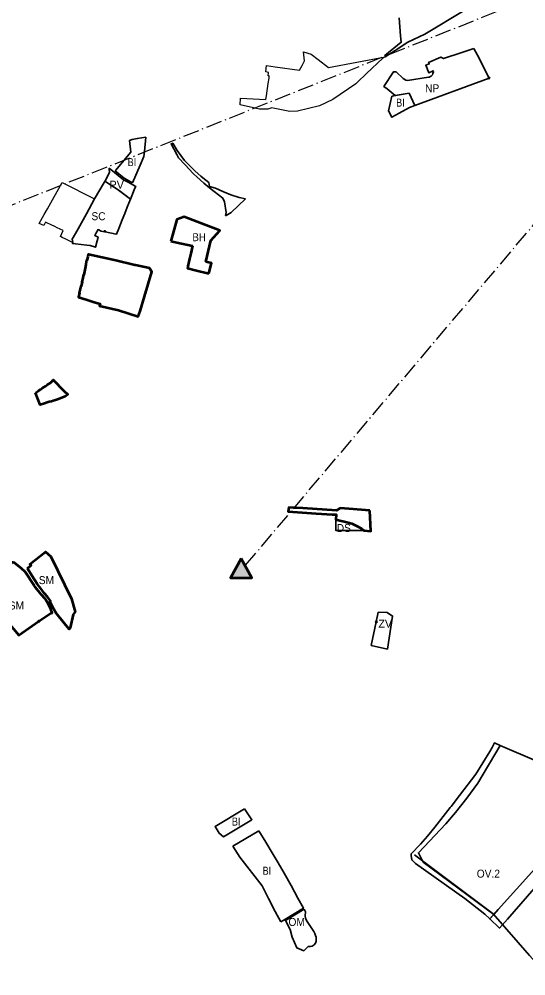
# Model space of a CAD drawing. Extents: x -650276 to -642489, y -1074311 to -1066658.
# Drawn here: x -646929 to -646170, y -1071706 to -1070271 of the extents above; entities that cross this region are included whole.
import ezdxf

# ---------------------------------------------------------------- set-up
doc = ezdxf.new("R2010")
doc.units = 0
doc.header["$LTSCALE"] = 4.8
doc.header["$PDMODE"] = 32
doc.header["$PDSIZE"] = 2.4
doc.linetypes.add('DOT_DASHED', pattern=[7.7, 5, -1.2, 0.3, -1.2])
for name, color, linetype, lineweight in [('1', 7, 'Continuous', 35), ('11', 7, 'Continuous', 35), ('12', 7, 'Continuous', 35), ('15', 7, 'Continuous', 35), ('17', 7, 'Continuous', 35), ('18', 7, 'Continuous', 35), ('2', 7, 'Continuous', 35), ('24', 7, 'Continuous', 35), ('40', 7, 'Continuous', 35), ('48', 7, 'Continuous', 35), ('54', 7, 'Continuous', 35), ('55', 7, 'Continuous', 53), ('60', 7, 'Continuous', 53), ('61', 7, 'Continuous', 25)]:
    doc.layers.add(name, color=color, linetype=linetype, lineweight=lineweight)
doc.layers.add('62', color=7, linetype='Continuous')
doc.layers.add('63', color=7, linetype='Continuous')

msp = doc.modelspace()

# ---------------------------------------------------------------- hatches: boundary and pattern name
at = {"layer": '55'}
msp.add_hatch(color=256, dxfattribs=at).paths.add_polyline_path([(-646596.857, -1071079.969), (-646612.808, -1071108.615), (-646580.424, -1071108.615)])

# ---------------------------------------------------------------- linework, layer by layer
at = {"layer": '1'}
msp.add_line((-646665.42, -1070647.54), (-646645.03, -1070652.34), dxfattribs=at)
for points in [[(-646655.95, -1070577.64), (-646682.29, -1070567.36), (-646692.98, -1070571.45), (-646701.87, -1070603.92)], [(-646649.71, -1070634.85), (-646642.32, -1070603.3), (-646628.69, -1070588.27), (-646655.95, -1070577.64)], [(-646701.87, -1070603.92), (-646693.18, -1070605.83), (-646669.59, -1070611.01), (-646672.13, -1070622.41), (-646673.91, -1070630.38), (-646676.414, -1070641.58)], [(-646676.414, -1070641.58), (-646676.81, -1070643.36), (-646677.13, -1070644.78), (-646665.42, -1070647.54)], [(-646645.03, -1070652.34), (-646641.09, -1070636.89), (-646649.71, -1070634.85)]]:
    msp.add_lwpolyline(points, dxfattribs=at)
at = {"layer": '11'}
msp.add_lwpolyline([(-646066.165, -1071422.155), (-646153.5, -1071383.85), (-646208.577, -1071360.044), (-646241.68, -1071416.887), (-646258.487, -1071439.265), (-646275.615, -1071460.886), (-646289.976, -1071477.514), (-646330.914, -1071521.11), (-646324, -1071535), (-646217.978, -1071613.552), (-646211.407, -1071606.247), (-646156.471, -1071545.166), (-646094.063, -1071471.007)], close=True, dxfattribs=at)
at = {"layer": '12'}
msp.add_lwpolyline([(-646502.39, -1071605.72), (-646530.27, -1071622.79), (-646522.99, -1071636.22), (-646520.32, -1071647.59), (-646513.43, -1071663.64), (-646502.53, -1071667.82), (-646496.06, -1071661.5), (-646492.89, -1071661.75), (-646490.07, -1071660.88), (-646487.36, -1071659.1), (-646485.29, -1071656.53), (-646484.15, -1071653.38), (-646483.97, -1071650.63), (-646484.38, -1071647.41), (-646485.2, -1071644.85), (-646486.31, -1071641.97), (-646487.56, -1071639.23), (-646497.83, -1071624.02), (-646499.829, -1071620.704), (-646500.289, -1071619.291), (-646500.83, -1071615.62), (-646500.34, -1071609.66)], close=True, dxfattribs=at)
at = {"layer": '15'}
for points in [[(-646623.95, -1070529.36), (-646634.85, -1070524.43), (-646644.2, -1070522.08), (-646645.31, -1070515.85), (-646654, -1070509), (-646656.83, -1070506.66), (-646665.457, -1070499.019), (-646667.42, -1070497.28), (-646681.6, -1070482.89), (-646692.74, -1070468.28), (-646699.26, -1070457.2), (-646701.65, -1070457.93), (-646693.119, -1070474.009), (-646690.316, -1070479.212), (-646680.44, -1070489.669), (-646668.361, -1070502.459), (-646667.369, -1070503.36), (-646662.895, -1070507.428), (-646652.352, -1070517.013), (-646643.895, -1070524.284), (-646637.158, -1070529.564), (-646624.211, -1070539.711), (-646621.729, -1070545.248), (-646619.34, -1070560.95), (-646619.99, -1070565.54), (-646619.15, -1070565.53), (-646611.41, -1070560.96), (-646590.2, -1070540.66), (-646599.81, -1070538.51), (-646611.88, -1070534.82)], [(-646275.615, -1071460.886), (-646258.487, -1071439.265), (-646241.68, -1071416.887), (-646208.577, -1071360.044), (-646217.049, -1071356.382), (-646220.61, -1071363.16), (-646223.77, -1071369.24), (-646245.1, -1071403.04), (-646269.2, -1071435.22), (-646281.99, -1071451.4), (-646283.52, -1071453.34), (-646293.87, -1071466.43), (-646306.14, -1071482.86), (-646317.52, -1071496.12), (-646327.97, -1071508.29), (-646341.88, -1071522.81), (-646341.66, -1071524.87), (-646340.93, -1071531.64), (-646335.3, -1071537.05), (-646261.46, -1071589.38), (-646231.43, -1071613.06), (-646223.928, -1071620.168), (-646217.978, -1071613.552), (-646324, -1071535), (-646330.914, -1071521.11), (-646289.976, -1071477.514), (-646275.615, -1071460.886)]]:
    msp.add_lwpolyline(points, close=True, dxfattribs=at)
for points in [[(-646794.59, -1070494.62), (-646794.53, -1070495.7), (-646793.75, -1070501.26), (-646800.6, -1070513.43), (-646800.94, -1070514.04)], [(-646755.84, -1070524.5), (-646754.52, -1070522.08), (-646765.96, -1070515.75), (-646770.95, -1070512.94), (-646773, -1070511.96), (-646794.59, -1070494.62)], [(-646800.94, -1070514.04), (-646788, -1070522.49), (-646782.63, -1070526.02)], [(-646782.63, -1070526.02), (-646779.68, -1070527.87), (-646762.71, -1070540.85), (-646755.84, -1070524.5)], [(-646156.471, -1071545.166), (-646211.407, -1071606.247), (-646223.928, -1071620.168), (-646209.322, -1071634.004), (-646197.398, -1071620.579), (-646077.593, -1071482.499)]]:
    msp.add_lwpolyline(points, dxfattribs=at)
at = {"layer": '17'}
msp.add_lwpolyline([(-646802.19, -1070516.26), (-646816.42, -1070540.49), (-646828.45, -1070562.89), (-646841.16, -1070585.79), (-646844.76, -1070592.54), (-646849.72, -1070600.98), (-646848.99, -1070606.28), (-646849.59, -1070607.4), (-646844.96, -1070607.98), (-646827.88, -1070610.12), (-646822.99, -1070610.51), (-646815.05, -1070613.14), (-646812.5, -1070603.78), (-646811.5, -1070600.29), (-646810.82, -1070598.23), (-646816.11, -1070595.8), (-646814.52, -1070592.78), (-646811.06, -1070586.67), (-646806.41, -1070589), (-646802.06, -1070589.93), (-646801.73, -1070588.37), (-646800.13, -1070588.71), (-646800.47, -1070590.28), (-646784.18, -1070593.76), (-646784, -1070593.34), (-646783.59, -1070593.52), (-646779.9, -1070584.92), (-646774.91, -1070571.88), (-646771.17, -1070562.7), (-646767.63, -1070553.09), (-646762.71, -1070540.85), (-646782.63, -1070526.02), (-646788, -1070522.49), (-646800.94, -1070514.04)], close=True, dxfattribs=at)
at = {"layer": '18'}
for points in [[(-646881.89, -1071077.03), (-646890.12, -1071069.67), (-646913.49, -1071088.22), (-646911.58, -1071089.9), (-646917.04, -1071094.75), (-646910.53, -1071105.18), (-646902.62, -1071117.58), (-646895.56, -1071126.84), (-646892.339, -1071131.481), (-646886.78, -1071137.25), (-646882.37, -1071143.39), (-646883.63, -1071144.15), (-646873.89, -1071161.58), (-646861.58, -1071177.05), (-646854.49, -1071185.87), (-646852.86, -1071183.98), (-646848.58, -1071163.95), (-646845.39, -1071159.98), (-646850.93, -1071140.54)], [(-646951.831, -1071107.765), (-646955.138, -1071114.466), (-646962.471, -1071129.325), (-646948.286, -1071172.534), (-646929.64, -1071194.58), (-646899.85, -1071173.89), (-646881.68, -1071161.83), (-646879.91, -1071161.24), (-646881.97, -1071155.84), (-646887.07, -1071145.66), (-646890.59, -1071140.39), (-646896.62, -1071133.93), (-646904.64, -1071123.54), (-646906.72, -1071120.46), (-646920.54, -1071099.98), (-646925.88, -1071094.68), (-646936.51, -1071086.33), (-646940.67, -1071085.15), (-646940.67, -1071085.15)]]:
    msp.add_lwpolyline(points, close=True, dxfattribs=at)
msp.add_point((-646899.85, -1071173.89), dxfattribs=at)
at = {"layer": '2'}
msp.add_line((-646609.21, -1071510.98), (-646570, -1071488.38), dxfattribs=at)
for points in [[(-646344.93, -1070382.33), (-646336.25, -1070400.875), (-646344.26, -1070403.84), (-646359.769, -1070412.361), (-646370.56, -1070418.29), (-646375.63, -1070408.76), (-646370.624, -1070386.792)], [(-646591.65, -1071454.91), (-646635.79, -1071481.6), (-646629.37, -1071491.74), (-646623.18, -1071496.99), (-646580.58, -1071471.48)]]:
    msp.add_lwpolyline(points, close=True, dxfattribs=at)
for points in [[(-646739.74, -1070447.98), (-646752.29, -1070450.28), (-646760.03, -1070451.56), (-646763.94, -1070452.95), (-646761.8, -1070470.4), (-646785.15, -1070498.05), (-646785.5, -1070498.47)], [(-646759.42, -1070516.37), (-646747.89, -1070489.87), (-646742.37, -1070477.2), (-646741.33, -1070469.79), (-646739.74, -1070447.98)], [(-646785.5, -1070498.47), (-646771.9, -1070509.4), (-646759.42, -1070516.37)], [(-646570, -1071488.38), (-646559.53, -1071505.12), (-646550.23, -1071520.88), (-646541.14, -1071536.3), (-646532.04, -1071551.72), (-646521.8, -1071570.34), (-646511.47, -1071589.11), (-646503.31, -1071603.95), (-646531.2, -1071621.07), (-646537.28, -1071624.8)], [(-646537.28, -1071624.8), (-646545.89, -1071609.07), (-646555.78, -1071589.66), (-646565.17, -1071570.4), (-646598.63, -1071527.8), (-646609.21, -1071510.98)]]:
    msp.add_lwpolyline(points, dxfattribs=at)
at = {"layer": '24'}
msp.add_lwpolyline([(-646454.59, -1071021.54), (-646454.59, -1071038), (-646412.54, -1071038.01), (-646415.61, -1071035.4), (-646421.58, -1071031.81), (-646430.91, -1071027.44)], close=True, dxfattribs=at)
at = {"layer": '40'}
for points in [[(-646377.5, -1071215.56), (-646369.76, -1071166.06), (-646377.87, -1071160.66), (-646391.07, -1071160.52), (-646394.05, -1071174.83)], [(-646394.05, -1071174.83), (-646401.64, -1071210.18), (-646377.5, -1071215.56)]]:
    msp.add_lwpolyline(points, dxfattribs=at)
msp.add_point((-646394.05, -1071174.83), dxfattribs=at)
at = {"layer": '48'}
msp.add_lwpolyline([(-646359.89, -1070269.01), (-646357.73, -1070296.13), (-646356.8, -1070305.73), (-646381.25, -1070325.85), (-646380.69, -1070327.47), (-646365.63, -1070318.37), (-646346.57, -1070305.88), (-646321.24, -1070293.85), (-646259.91, -1070256.89)], dxfattribs=at)
msp.add_lwpolyline([(-646247.667, -1070315.004), (-646267.3, -1070321.61), (-646293.14, -1070330.3), (-646297.4, -1070328.01), (-646315.84, -1070336.13), (-646314.84, -1070338.41), (-646319.95, -1070340.42), (-646315.46, -1070351.67), (-646308.791, -1070348.855), (-646308.59, -1070350.22), (-646309.18, -1070352.77), (-646309.99, -1070354.58), (-646311.82, -1070356.89), (-646314.6, -1070358.05), (-646315.7, -1070358.27), (-646347.49, -1070363.01), (-646349.76, -1070362.69), (-646353.81, -1070360.18), (-646364.34, -1070350.19), (-646368.4, -1070350.41), (-646382.67, -1070371.94), (-646377.86, -1070375.71), (-646365.7, -1070385.89), (-646344.93, -1070382.33), (-646336.35, -1070400.9), (-646225.15, -1070359.46), (-646242.56, -1070325.1)], close=True, dxfattribs=at)
msp.add_point((-646225.15, -1070359.46), dxfattribs=at)
at = {"layer": '54'}
msp.add_lwpolyline([(-646336.784, -1071524.232), (-646218.737, -1071612.767), (-646164.374, -1071674.897), (-645904.456, -1071961.331), (-645718.199, -1072151.712), (-645526.944, -1072343.922), (-645538, -1072384), (-645459, -1072440), (-645389, -1072483), (-645335, -1072526), (-645287, -1072569), (-645227, -1072617), (-645139.573, -1072694.628), (-645084.365, -1072788.086)], dxfattribs=at)
at = {"layer": '55', "linetype": 'DOT_DASHED', "lineweight": 25}
for p, q in [((-647060.176, -1070597.455), (-645765.418, -1070080.935)), ((-646590, -1071090), (-645744.292, -1070089.84))]:
    msp.add_line(p, q, dxfattribs=at)
at = {"layer": '55'}
msp.add_lwpolyline([(-646596.857, -1071079.969), (-646612.808, -1071108.615), (-646580.424, -1071108.615)], close=True, dxfattribs=at)
at = {"layer": '60'}
for points in [[(-646655.95, -1070577.64), (-646682.29, -1070567.36), (-646692.98, -1070571.45), (-646701.87, -1070603.92)], [(-646649.71, -1070634.85), (-646642.32, -1070603.3), (-646628.69, -1070588.27), (-646655.95, -1070577.64)], [(-646701.87, -1070603.92), (-646693.18, -1070605.83), (-646669.59, -1070611.01)], [(-646669.59, -1070611.01), (-646672.13, -1070622.41), (-646673.91, -1070630.38), (-646676.414, -1070641.58)], [(-646676.414, -1070641.58), (-646676.81, -1070643.36), (-646677.13, -1070644.78), (-646665.42, -1070647.54), (-646645.03, -1070652.34)], [(-646645.03, -1070652.34), (-646641.09, -1070636.89), (-646649.71, -1070634.85)]]:
    msp.add_lwpolyline(points, dxfattribs=at)
for points in [[(-646825.54, -1070624.03), (-646826.12, -1070623.9), (-646826.45, -1070627.3), (-646827.98, -1070632.83), (-646828.22, -1070632.77), (-646829.55, -1070638.78), (-646829.55, -1070638.78), (-646829.3, -1070638.83), (-646830.51, -1070644.3), (-646830.26, -1070644.35), (-646832.46, -1070654.31), (-646832.7, -1070654.26), (-646834.27, -1070661.39), (-646834.27, -1070661.39), (-646834.4, -1070661.35), (-646835.23, -1070665.08), (-646835.1, -1070665.12), (-646836.6, -1070671.54), (-646836.6, -1070671.54), (-646836.87, -1070671.46), (-646839.27, -1070681.62), (-646838.96, -1070681.72), (-646840.36, -1070687.86), (-646828.7, -1070691.73), (-646816.84, -1070695.43), (-646808.09, -1070698.19), (-646808.76, -1070701.11), (-646780.44, -1070707.59), (-646751.23, -1070717), (-646748.04, -1070709.23), (-646741.52, -1070687.22), (-646730.66, -1070650.07), (-646734.18, -1070644.6), (-646755.21, -1070639.87), (-646755.84, -1070639.88), (-646784.62, -1070633.19)], [(-646904.8, -1070831.23), (-646900.57, -1070828.42), (-646900.09, -1070828.1), (-646897.34, -1070826.28), (-646894.84, -1070824.62), (-646892.34, -1070822.96), (-646889.85, -1070821.3), (-646887.3, -1070819.61), (-646884.68, -1070817.87), (-646882.18, -1070816.21), (-646878.66, -1070812.72), (-646878.61, -1070812.14), (-646862.56, -1070828.29), (-646856.41, -1070834.13), (-646860.55, -1070836.71), (-646871.78, -1070841.33), (-646875.05, -1070842.32), (-646878.26, -1070843.29), (-646881.11, -1070844.21), (-646884.27, -1070845.17), (-646887.32, -1070846.14), (-646891.42, -1070847.44), (-646897.71, -1070849.39), (-646901.26, -1070840.31)], [(-646403.81, -1071007.7), (-646435.28, -1071005.2), (-646448.48, -1071004.25), (-646453.7, -1071007.79), (-646504.25, -1071004.54), (-646516.78, -1071003.78), (-646525.4, -1071003.29), (-646526.31, -1071009.55), (-646484.27, -1071012.11), (-646460.09, -1071013.61), (-646454.02, -1071013.98), (-646454.59, -1071021.54), (-646436.15, -1071025.97), (-646430.91, -1071027.44), (-646421.58, -1071031.81), (-646415.61, -1071035.4), (-646412.54, -1071038.01), (-646402.09, -1071038.95)], [(-646917.04, -1071094.75), (-646911.58, -1071089.9), (-646913.49, -1071088.22), (-646906.17, -1071082.72), (-646890.12, -1071069.67), (-646881.89, -1071077.03), (-646850.93, -1071140.54), (-646845.39, -1071159.98), (-646848.58, -1071163.95), (-646852.86, -1071183.98), (-646854.49, -1071185.87), (-646861.58, -1071177.05), (-646873.89, -1071161.58), (-646877.226, -1071155.611), (-646883.63, -1071144.15), (-646882.37, -1071143.39), (-646886.78, -1071137.25), (-646892.11, -1071131.81), (-646895.56, -1071126.84), (-646902.62, -1071117.58), (-646910.53, -1071105.18)], [(-646951.831, -1071107.765), (-646955.138, -1071114.466), (-646962.471, -1071129.325), (-646948.286, -1071172.534), (-646929.64, -1071194.58), (-646899.85, -1071173.89), (-646881.68, -1071161.83), (-646879.91, -1071161.24), (-646881.97, -1071155.84), (-646887.07, -1071145.66), (-646890.59, -1071140.39), (-646896.62, -1071133.93), (-646904.64, -1071123.54), (-646906.72, -1071120.46), (-646920.54, -1071099.98), (-646925.88, -1071094.68), (-646936.51, -1071086.33), (-646940.67, -1071085.15)]]:
    msp.add_lwpolyline(points, close=True, dxfattribs=at)
at = {"layer": '61'}
for points in [[(-646503.36, -1070320.39), (-646491.81, -1070323.54), (-646481.1, -1070331.76), (-646465.85, -1070343.46), (-646380.69, -1070327.47), (-646384.18, -1070329.58), (-646408.97, -1070352.57), (-646422.07, -1070365.6), (-646424.74, -1070368.25), (-646459.18, -1070391.48), (-646479.26, -1070401.17), (-646512.38, -1070409.18), (-646523.89, -1070409.54), (-646541.25, -1070406.02), (-646545.97, -1070405.06), (-646550.91, -1070404.27), (-646556.66, -1070406.07), (-646569.39, -1070406.06), (-646598.16, -1070399.848), (-646597.44, -1070389.891), (-646559.41, -1070391.82), (-646558.74, -1070386.15), (-646556, -1070367.59), (-646554.86, -1070359.63), (-646554.86, -1070359.63), (-646554.42, -1070356.22), (-646556.1, -1070356), (-646555.42, -1070350.94), (-646559.71, -1070350.35), (-646558.49, -1070340.9), (-646545.77, -1070342.7), (-646509.08, -1070347.79), (-646505.44, -1070340.51), (-646501.94, -1070333.51)], [(-646867.54, -1070597.11), (-646863.26, -1070588.3), (-646872.19, -1070583.97), (-646876.02, -1070582.12), (-646877.88, -1070581.22), (-646879.541, -1070580.417), (-646889.9, -1070575.41), (-646892.4, -1070580.64), (-646899.2, -1070577.61), (-646891.65, -1070564.15), (-646886.72, -1070555.37), (-646864.73, -1070516.2), (-646816.66, -1070540.37), (-646816.42, -1070540.49), (-646828.45, -1070562.89), (-646838.95, -1070581.53), (-646841.16, -1070585.79), (-646844.76, -1070592.54), (-646849.72, -1070600.98), (-646849.72, -1070600.98), (-646848.99, -1070606.28), (-646852.3, -1070604.63), (-646859.48, -1070601.1), (-646865.02, -1070598.34)]]:
    msp.add_lwpolyline(points, close=True, dxfattribs=at)

# ---------------------------------------------------------------- texts
at = {"layer": '62'}
for s, width, p in [('NP', 0.95, (-646320.99, -1070380.819)), ('BI', 0.85, (-646364.337, -1070402.32)), ('BI', 0.85, (-646766.828, -1070491.569)), ('SC', 0.95, (-646821.06, -1070572.645)), ('DS', 0.95, (-646453.386, -1071040.148)), ('SM', 0.95, (-646899.938, -1071118.245)), ('BI', 0.85, (-646610.515, -1071480.22)), ('BI', 0.85, (-646564.529, -1071553.971)), ('OV.2', 0.95, (-646243.486, -1071558.306)), ('OM', 0.95, (-646525.703, -1071630.756))]:
    msp.add_text(s, height=12, dxfattribs=dict(at, width=width)).set_placement(p)
for s, p in [('PV', (-646793.831, -1070525.433)), ('ZV', (-646390.931, -1071183.591))]:
    msp.add_text(s, height=12, dxfattribs=at).set_placement(p)
at = {"layer": '63'}
for s, width, p in [('BH', 0.9, (-646669.646, -1070604.101)), ('SM', 0.95, (-646944.938, -1071156.245))]:
    msp.add_text(s, height=12, dxfattribs=dict(at, width=width)).set_placement(p)

doc.saveas('drawing.dxf')
